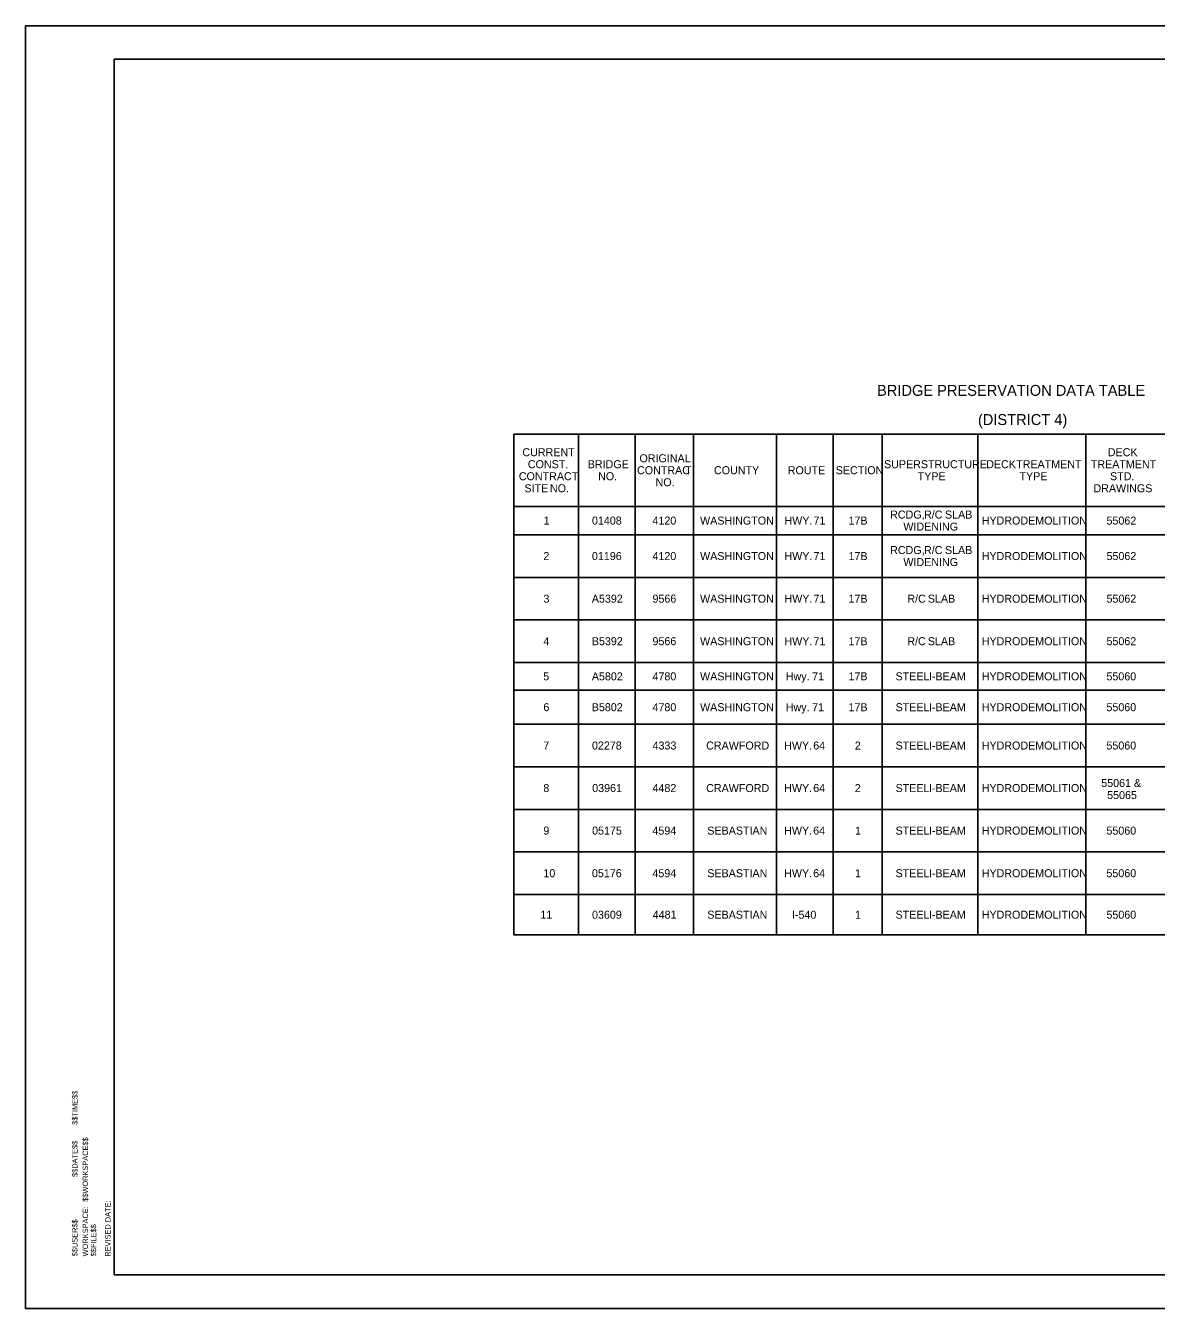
# Model space of a CAD drawing. Extents: x 16 to 1228740, y 11 to 152440.
# Drawn here: x 15.657 to 17.273, y 10.709 to 12.543 of the extents above; entities that cross this region are included whole.
import ezdxf

# ---------------------------------------------------------------- set-up
doc = ezdxf.new("R2010")
doc.units = 0
doc.layers.add('B_Text', color=7, linetype='Continuous')
doc.layers.add('R_Border', color=7, linetype='Continuous')

msp = doc.modelspace()

# ---------------------------------------------------------------- linework, layer by layer
at = {"layer": 'B_Text'}
for p, q in [((16.3546, 11.9591), (16.3546, 11.9591)), ((16.3546, 11.9591), (17.8411, 11.9591)), ((16.3546, 11.2432), (16.3546, 11.9591)), ((16.4469, 11.2432), (16.4469, 11.9591)), ((16.528, 11.2432), (16.528, 11.9591)), ((16.6111, 11.2432), (16.6111, 11.9591)), ((16.7298, 11.2432), (16.7298, 11.9591)), ((16.8109, 11.2432), (16.8109, 11.9591)), ((16.8809, 11.2432), (16.8809, 11.9591)), ((17.0178, 11.2432), (17.0178, 11.9591)), ((17.1719, 11.2432), (17.1719, 11.9591)), ((16.3546, 11.8557), (17.8411, 11.8557)), ((16.3546, 11.8151), (17.8411, 11.8151)), ((16.3546, 11.7543), (17.8411, 11.7543)), ((16.3546, 11.6934), (17.8411, 11.6934)), ((16.3546, 11.6326), (17.8411, 11.6326)), ((16.3546, 11.5931), (17.8411, 11.5931)), ((16.3546, 11.5444), (17.8411, 11.5444)), ((16.3546, 11.4835), (17.8411, 11.4835)), ((16.3546, 11.4227), (17.8411, 11.4227)), ((16.3546, 11.3619), (17.8411, 11.3619)), ((16.3546, 11.301), (17.8411, 11.301)), ((16.3546, 11.2432), (17.8411, 11.2432))]:
    msp.add_line(p, q, dxfattribs=at)
at = {"layer": 'R_Border'}
for p, q in [((15.7833, 12.4948), (18.4422, 12.4948)), ((15.7833, 10.7576), (15.7833, 12.4948)), ((15.6959, 10.7451), (15.6959, 10.7451)), ((18.4422, 10.7576), (15.7833, 10.7576))]:
    msp.add_line(p, q, dxfattribs=at)
msp.add_lwpolyline([(15.6569, 12.5428), (18.4903, 12.5428), (18.4903, 10.7095), (15.6569, 10.7095)], close=True, dxfattribs=at)

# ---------------------------------------------------------------- texts
at = {"layer": 'B_Text'}
for s, height, p in [('BRIDGE PRESERVATION DATA TABLE ', 0.015625, (16.8736, 12.0137)), ('(DISTRICT 4)', 0.015625, (17.0178, 11.972)), ('CURRENT', 0.01144, (16.3668, 11.9274)), ('DECK', 0.01144, (17.2034, 11.9274)), ('CONST.', 0.01144, (16.3746, 11.9103)), ('BRIDGE', 0.01144, (16.4602, 11.9103)), ('ORIGINAL', 0.01144, (16.5341, 11.9188)), ('SUPERSTRUCTURE', 0.01144, (16.8836, 11.9103)), ('DECK', 0.01144, (17.0296, 11.9103)), (' TREATMENT', 0.01144, (17.0681, 11.9103)), ('TREATMENT', 0.01144, (17.1791, 11.9103)), ('CONTRACT', 0.01144, (16.3617, 11.8931)), ('NO.', 0.01144, (16.475, 11.8931)), ('CONTRAC', 0.01144, (16.5306, 11.9017)), ('T', 0.0114, (16.5993, 11.9017)), ('COUNTY', 0.01144, (16.6406, 11.9017)), ('ROUTE', 0.01144, (16.746, 11.9017)), ('SECTION', 0.01144, (16.8146, 11.9017)), ('TYPE', 0.01144, (16.9317, 11.8931)), ('TYPE', 0.01144, (17.0772, 11.8931)), ('STD.', 0.01144, (17.2066, 11.8931)), ('SITE', 0.01144, (16.3697, 11.8759)), (' NO.', 0.01144, (16.4019, 11.8759)), ('NO.', 0.01144, (16.5571, 11.8845)), ('DRAWINGS', 0.01144, (17.1829, 11.8759)), ('RCDG,', 0.01144, (16.8923, 11.8383)), (' R/C', 0.01144, (16.9365, 11.8383)), (' SLAB', 0.01144, (16.9664, 11.8383)), ('1', 0.0114, (16.3971, 11.8297)), ('01408', 0.01144, (16.4662, 11.8297)), ('4120', 0.01144, (16.5527, 11.8297)), ('WASHINGTON', 0.01144, (16.6207, 11.8297)), ('HWY.', 0.01144, (16.7413, 11.8297)), (' 71', 0.01144, (16.7785, 11.8297)), ('17B', 0.01144, (16.8328, 11.8297)), ('WIDENING', 0.01144, (16.9112, 11.8211)), ('HYDRODEMOLITION', 0.01144, (17.0232, 11.8297)), ('55062', 0.01144, (17.2015, 11.8297)), ('2', 0.0114, (16.3968, 11.779)), ('01196', 0.01144, (16.4662, 11.779)), ('4120', 0.01144, (16.5527, 11.779)), ('WASHINGTON', 0.01144, (16.6207, 11.779)), ('HWY.', 0.01144, (16.7413, 11.779)), (' 71', 0.01144, (16.7785, 11.779)), ('17B', 0.01144, (16.8328, 11.779)), ('RCDG,', 0.01144, (16.8923, 11.7876)), (' R/C', 0.01144, (16.9365, 11.7876)), (' SLAB', 0.01144, (16.9664, 11.7876)), ('HYDRODEMOLITION', 0.01144, (17.0232, 11.779)), ('55062', 0.01144, (17.2015, 11.779)), ('WIDENING', 0.01144, (16.9112, 11.7704)), ('3', 0.0114, (16.3969, 11.7181)), ('A5392', 0.01144, (16.466, 11.7181)), ('9566', 0.01144, (16.5527, 11.7181)), ('WASHINGTON', 0.01144, (16.6207, 11.7181)), ('HWY.', 0.01144, (16.7413, 11.7181)), (' 71', 0.01144, (16.7785, 11.7181)), ('17B', 0.01144, (16.8328, 11.7181)), ('R/C', 0.01144, (16.9169, 11.7181)), (' SLAB', 0.01144, (16.9419, 11.7181)), ('HYDRODEMOLITION', 0.01144, (17.0232, 11.7181)), ('55062', 0.01144, (17.2015, 11.7181)), ('4', 0.0114, (16.3969, 11.6573)), ('B5392', 0.01144, (16.466, 11.6573)), ('9566', 0.01144, (16.5527, 11.6573)), ('WASHINGTON', 0.01144, (16.6207, 11.6573)), ('HWY.', 0.01144, (16.7413, 11.6573)), (' 71', 0.01144, (16.7785, 11.6573)), ('17B', 0.01144, (16.8328, 11.6573)), ('R/C', 0.01144, (16.9169, 11.6573)), (' SLAB', 0.01144, (16.9419, 11.6573)), ('HYDRODEMOLITION', 0.01144, (17.0232, 11.6573)), ('55062', 0.01144, (17.2015, 11.6573)), ('5', 0.0114, (16.3966, 11.6071)), ('A5802', 0.01144, (16.466, 11.6071)), ('4780', 0.01144, (16.5527, 11.6071)), ('WASHINGTON', 0.01144, (16.6207, 11.6071)), ('Hwy.', 0.01144, (16.7432, 11.6071)), (' 71', 0.01144, (16.7766, 11.6071)), ('17B', 0.01144, (16.8328, 11.6071)), ('STEEL', 0.01144, (16.9001, 11.6071)), (' I-BEAM', 0.01144, (16.9435, 11.6071)), ('HYDRODEMOLITION', 0.01144, (17.0232, 11.6071)), ('55060', 0.01144, (17.2014, 11.6071)), ('6', 0.0114, (16.3968, 11.563)), ('B5802', 0.01144, (16.4659, 11.563)), ('4780', 0.01144, (16.5527, 11.563)), ('WASHINGTON', 0.01144, (16.6207, 11.563)), ('Hwy.', 0.01144, (16.7432, 11.563)), (' 71', 0.01144, (16.7766, 11.563)), ('17B', 0.01144, (16.8328, 11.563)), ('STEEL', 0.01144, (16.9001, 11.563)), (' I-BEAM', 0.01144, (16.9435, 11.563)), ('HYDRODEMOLITION', 0.01144, (17.0232, 11.563)), ('55060', 0.01144, (17.2014, 11.563)), ('7', 0.0114, (16.3967, 11.5082)), ('02278', 0.01144, (16.4662, 11.5082)), ('4333', 0.01144, (16.5528, 11.5082)), ('CRAWFORD', 0.01144, (16.6294, 11.5082)), ('HWY.', 0.01144, (16.7409, 11.5082)), (' 64', 0.01144, (16.7781, 11.5082)), ('2', 0.0114, (16.8419, 11.5082)), ('STEEL', 0.01144, (16.9001, 11.5082)), (' I-BEAM', 0.01144, (16.9435, 11.5082)), ('HYDRODEMOLITION', 0.01144, (17.0232, 11.5082)), ('55060', 0.01144, (17.2014, 11.5082)), ('8', 0.0114, (16.3967, 11.4474)), ('03961', 0.01144, (16.4666, 11.4474)), ('4482', 0.01144, (16.5527, 11.4474)), ('CRAWFORD', 0.01144, (16.6294, 11.4474)), ('HWY.', 0.01144, (16.7409, 11.4474)), (' 64', 0.01144, (16.7781, 11.4474)), ('2', 0.0114, (16.8419, 11.4474)), ('STEEL', 0.01144, (16.9001, 11.4474)), (' I-BEAM', 0.01144, (16.9435, 11.4474)), ('HYDRODEMOLITION', 0.01144, (17.0232, 11.4474)), ('55061 &', 0.01144, (17.194, 11.4546)), ('55065', 0.01144, (17.2024, 11.4374)), ('9', 0.0114, (16.3967, 11.3866)), ('05175', 0.01144, (16.4664, 11.3866)), ('4594', 0.01144, (16.5526, 11.3866)), ('SEBASTIAN', 0.01144, (16.631, 11.3866)), ('HWY.', 0.01144, (16.7409, 11.3866)), (' 64', 0.01144, (16.7781, 11.3866)), ('1', 0.0114, (16.8422, 11.3866)), ('STEEL', 0.01144, (16.9001, 11.3866)), (' I-BEAM', 0.01144, (16.9435, 11.3866)), ('HYDRODEMOLITION', 0.01144, (17.0232, 11.3866)), ('55060', 0.01144, (17.2014, 11.3866)), ('10', 0.01144, (16.3968, 11.3257)), ('05176', 0.01144, (16.4662, 11.3257)), ('4594', 0.01144, (16.5526, 11.3257)), ('SEBASTIAN', 0.01144, (16.631, 11.3257)), ('HWY.', 0.01144, (16.7409, 11.3257)), (' 64', 0.01144, (16.7781, 11.3257)), ('1', 0.0114, (16.8422, 11.3257)), ('STEEL', 0.01144, (16.9001, 11.3257)), (' I-BEAM', 0.01144, (16.9435, 11.3257)), ('HYDRODEMOLITION', 0.01144, (17.0232, 11.3257)), ('55060', 0.01144, (17.2014, 11.3257)), ('11', 0.01144, (16.3925, 11.2664)), ('03609', 0.01144, (16.4663, 11.2664)), ('4481', 0.01144, (16.553, 11.2664)), ('SEBASTIAN', 0.01144, (16.631, 11.2664)), ('I-540', 0.01144, (16.752, 11.2664)), ('1', 0.0114, (16.8422, 11.2664)), ('STEEL', 0.01144, (16.9001, 11.2664)), (' I-BEAM', 0.01144, (16.9435, 11.2664)), ('HYDRODEMOLITION', 0.01144, (17.0232, 11.2664)), ('55060', 0.01144, (17.2014, 11.2664))]:
    msp.add_text(s, height=height, dxfattribs=at).set_placement(p)
at = {"layer": 'R_Border'}
for s, p in [('$$TIME$$', (15.7311, 10.9718)), ('$$DATE$$', (15.7311, 10.8973)), ('$$WORKSPACE$$', (15.746, 10.8618)), ('REVISED DATE:', (15.7782, 10.7833)), ('WORKSPACE:', (15.746, 10.7838)), ('$$USER$$', (15.7311, 10.7839)), ('$$FILE$$', (15.7578, 10.7839))]:
    msp.add_text(s, height=0.00765, rotation=90, dxfattribs=at).set_placement(p)

doc.saveas('drawing.dxf')
